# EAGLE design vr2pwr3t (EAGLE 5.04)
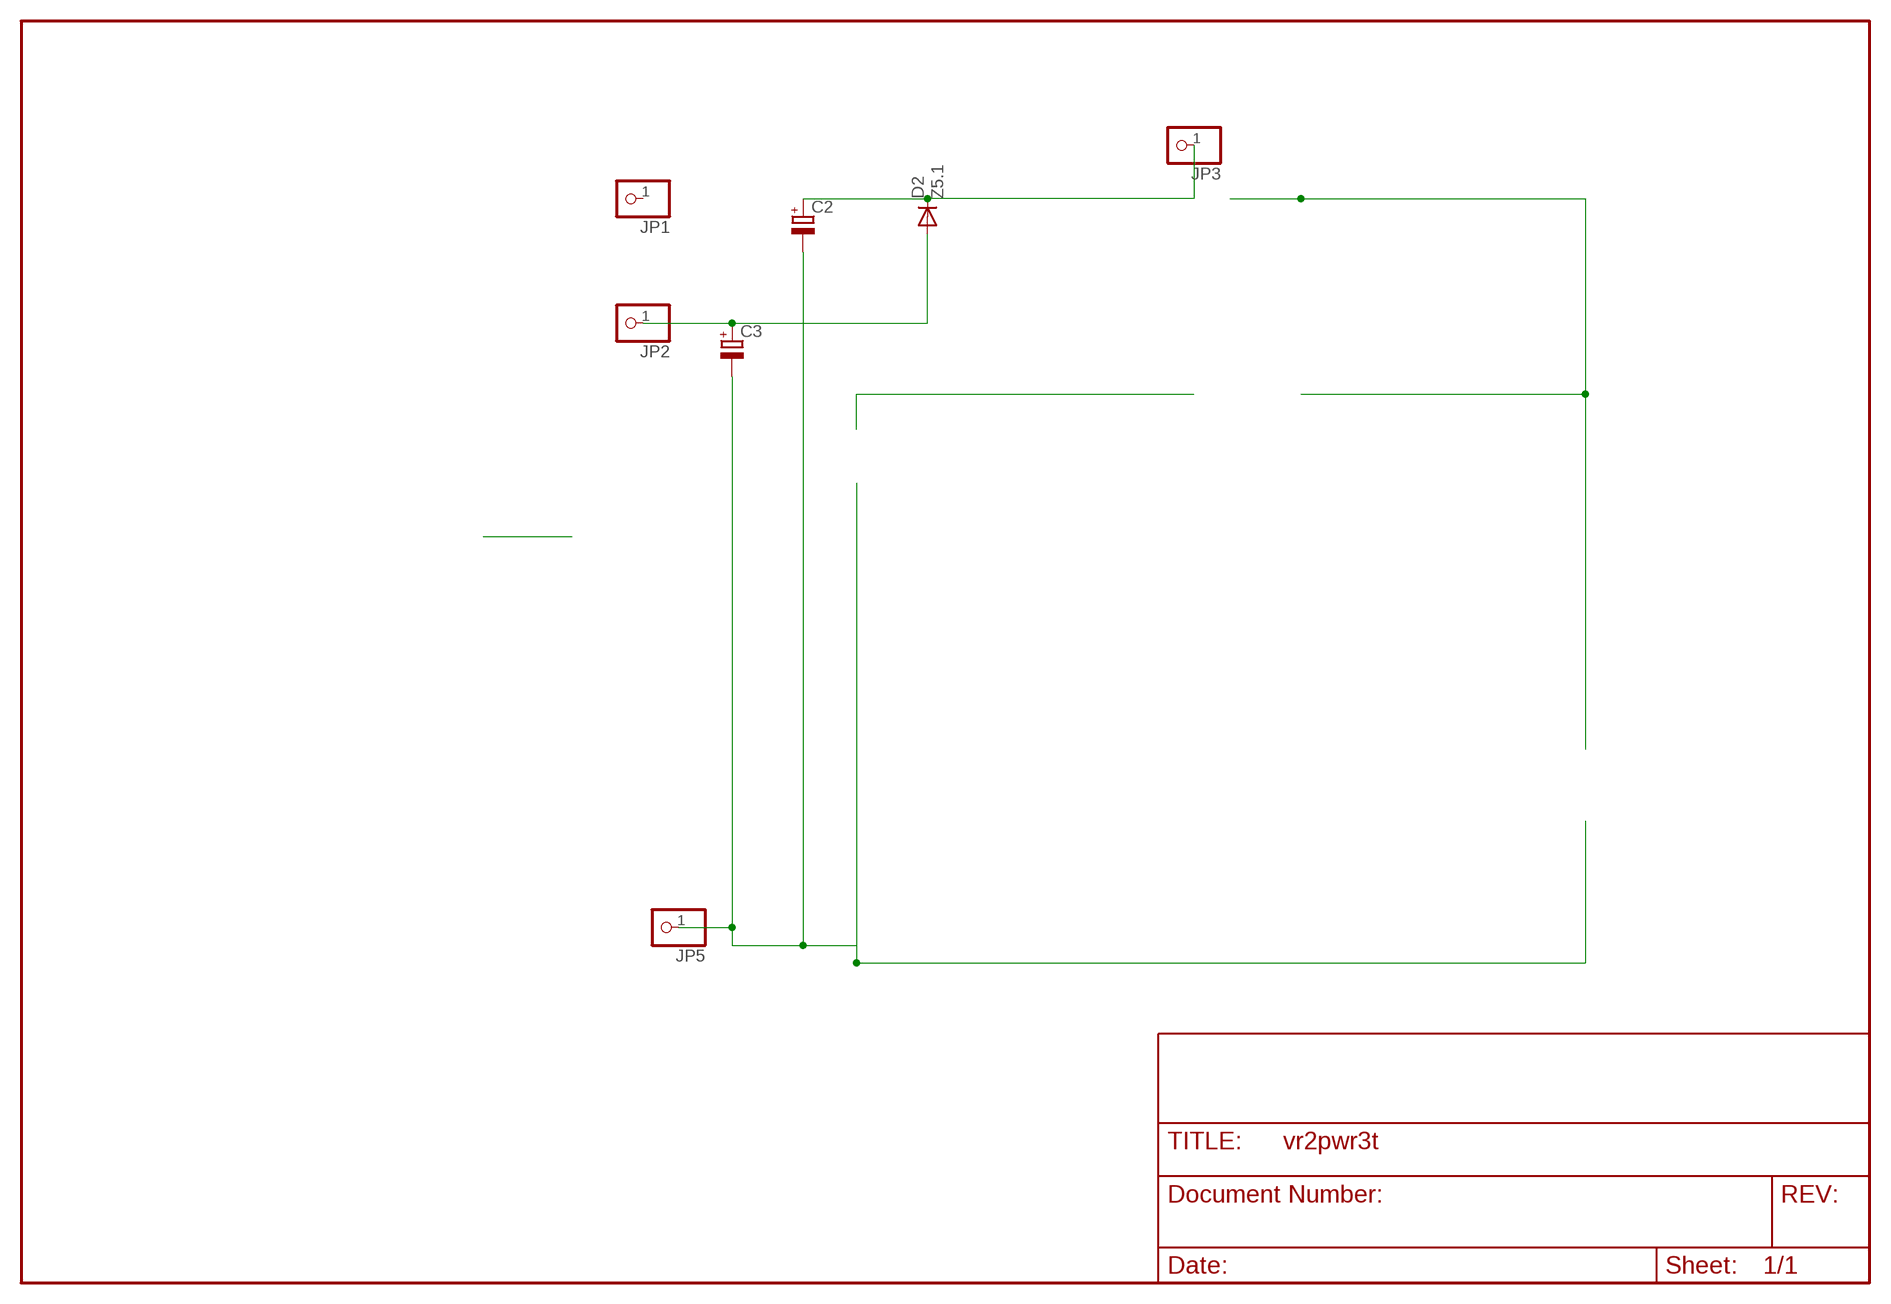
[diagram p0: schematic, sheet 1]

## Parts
C2  CPOL-EUE2.5-7  [E2,5-7]
C3  CPOL-EUE2-4  [E2-4]
D2  Z5.1  DIODE-D-2.5  [D-2.5]
JP1  PINHD-1X1  [1X01]
JP2  PINHD-1X1  [1X01]
JP3  PINHD-1X1  [1X01]
JP5  PINHD-1X1  [1X01]

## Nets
LOAD: C2.+ D2.C JP3.1
N$4: C3.+ D2.A JP2.1
N$30: C2.- C3.- JP5.1
Unconnected: JP1.1

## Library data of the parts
C2 C3 = rcl(2):CPOL-EU: POLARIZED CAPACITOR, European symbol
D2 = diode:DIODE-: DIODE
JP1-JP3 JP5 = pinhead:PINHD-1X1: PIN HEADER

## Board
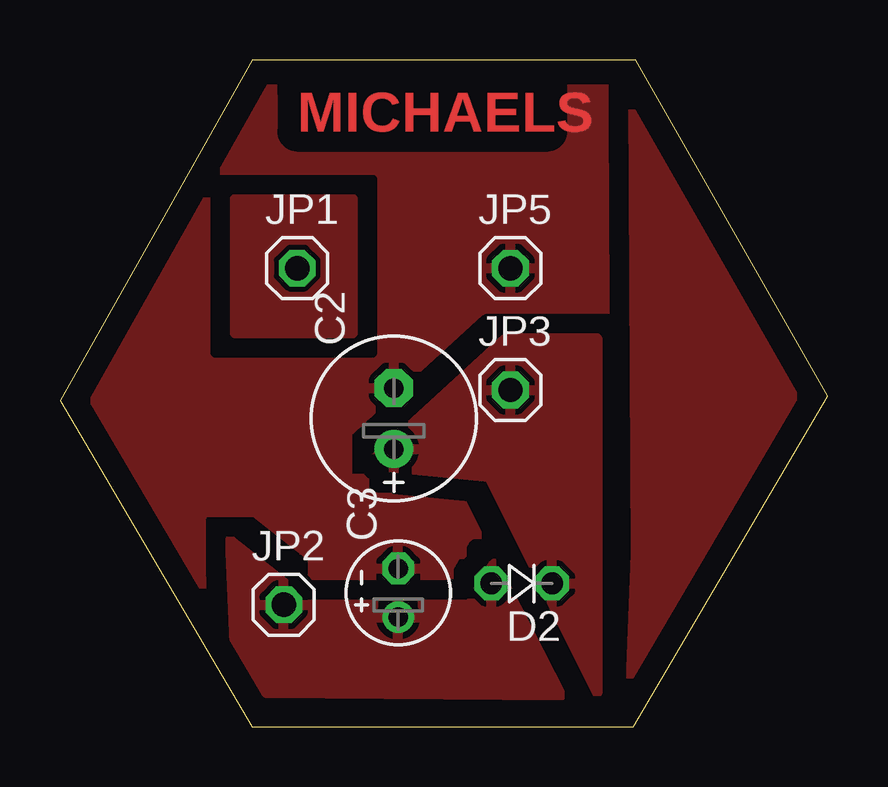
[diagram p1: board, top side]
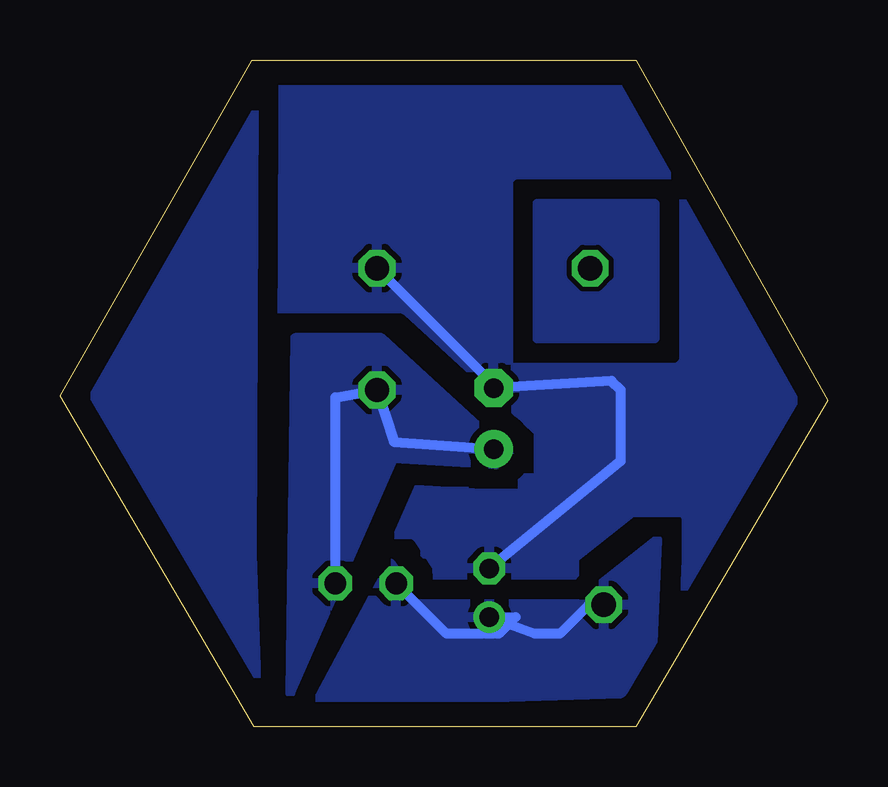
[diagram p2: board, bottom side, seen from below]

Size 32 x 27.8 mm. Coordinates in mm from the lower left corner, seen from the top.
Outline: 8,0 23.9,0 32,13.8 24,27.8 8,27.8 0,13.6 8,0
Copper layers (1*16): Top 0.035mm / dielectric 1.5mm / Bottom 0.035mm
Design rules "default": minimum track width 10mil, minimum drill 24mil, track to track 8mil, track to pad 8mil, pad to pad 8mil, via to via 8mil, smd to smd 8mil, copper to edge 40mil, drill to drill 8mil, minimum pad ring 10mil, minimum via ring 8mil, stop-mask expansion 4mil, vias tented up to drill 0mil, thermal gap 10mil

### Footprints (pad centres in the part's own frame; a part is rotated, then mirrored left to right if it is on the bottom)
E2,5-7 = drill 0.813 pad 1.6 round: + -1.27,0 | drill 0.813 pad 1.6 octagon: - 1.27,0
E2-4 = drill 0.813 pad 1.27 round: + -1.016,0 | drill 0.813 pad 1.27 octagon: - 1.016,0
D-2.5 = drill 0.9 octagon: A 1.27,0; C -1.27,0
1X01 = drill 1.016 octagon: 1 0,0

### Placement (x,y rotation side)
C2  13.92,12.85 90 top
C3  14.1,5.58 90 top
D2  19.25,5.98 180 top
JP1  9.89,19.12 0 top
JP2  9.33,5.09 0 top
JP3  18.78,14.04 0 top
JP5  18.78,19.12 0 top

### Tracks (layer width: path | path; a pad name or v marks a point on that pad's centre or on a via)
LOAD
  Bottom 0.406: D2.C 20.52,13.74 JP3.1 18.08,11.88 C2.+
  pour Bottom: 18.6,16.2 22.2,16.2 22.4,1.4 18.1,11.2 12.8,10.9
  pour Top: 18.6,16.2 22.4,16.2 22.4,1.4 17.9,10.4 12.8,10.9
N$1
  pour Top: 9.6,16.4 7.3,16.4 7.3,22 12.2,22 12.2,16.4
  pour Bottom: 9.5,16.2 7.2,16.2 7.2,21.8 12.1,21.8 12.1,16.2
  pour Top (rank 2): 23.8,1.9 24,7.2 23.9,26.2 31.3,14.2 27.4,7
  pour Bottom (rank 2): 23.8,1.9 24,7.2 23.9,26.2 31.3,14.2 27.4,7
N$4
  Bottom 0.406: JP2.1 9.95,5.09 11.16,3.88 12.21,3.88 C3.+ 13,4.58 13.7,3.88 15.88,3.88 D2.A
  pour Bottom: 7.1,7.8 10.5,5.1 17.1,5.1 18.2,6.8 21.3,1 8.6,1.4 7.3,3
  pour Top: 7.1,7.8 10.5,5.1 17.1,5.1 18.1,6.8 20.9,1.3 8.6,1.4 7.3,3
N$30
  Bottom 0.406: JP5.1 14.08,14.42 C2.- 9,14.42 8.62,14.04 8.62,11.08 C3.-
  pour Bottom (isolate 0.813, rank 3): 8.4,27.2 24.7,27.2 26,25.9 31.5,13.9 23.6,0.5 8.6,0.6 0.7,13.3 7.3,25
  pour Top (isolate 0.813, rank 3): 8.4,27.2 24.7,27.2 26,25.9 31.5,13.9 23.6,0.5 8.6,0.6 0.7,13.3 7.3,25

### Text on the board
Top: MICHAELS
